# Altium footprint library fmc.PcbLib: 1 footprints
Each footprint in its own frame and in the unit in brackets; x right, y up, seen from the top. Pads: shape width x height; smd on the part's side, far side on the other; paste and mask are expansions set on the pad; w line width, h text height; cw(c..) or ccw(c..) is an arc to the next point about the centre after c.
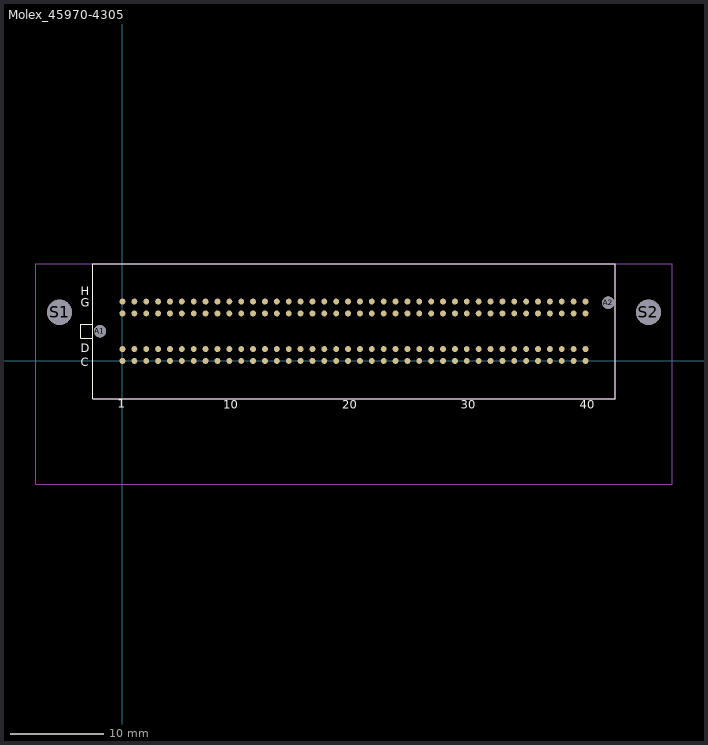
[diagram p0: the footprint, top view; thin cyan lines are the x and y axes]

## Molex_45970-4305 [mm] "1.27mm Pitch, SEARAY* Plug, 400 Circuits, 3.50mm Unmated Height, 10 Rows, with Pegs, Solder Charge™ Lead-Free, with Voids, per VITA-57"
pads (164):
  round 0.63 smd: 1(0,0) C2(1.27,0) C3(2.54,0) C4(3.81,0) C5(5.08,0) C6(6.35,0) C7(7.62,0) C8(8.89,0) C9(10.16,0) C10(11.43,0) C11(12.7,0) C12(13.97,0) C13(15.24,0) C14(16.51,0) C15(17.78,0) C16(19.05,0) C17(20.32,0) C18(21.59,0) C19(22.86,0) C20(24.13,0) C21(25.4,0) C22(26.67,0) C23(27.94,0) C24(29.21,0) C25(30.48,0) C26(31.75,0) C27(33.02,0) C28(34.29,0) C29(35.56,0) C30(36.83,0) C31(38.1,0) C32(39.37,0) C33(40.64,0) C34(41.91,0) C35(43.18,0) C36(44.45,0) C37(45.72,0) C38(46.99,0) C39(48.26,0) C40(49.53,0) D1(0,1.27) D2(1.27,1.27) D3(2.54,1.27) D4(3.81,1.27) D5(5.08,1.27) D6(6.35,1.27) D7(7.62,1.27) D8(8.89,1.27) D9(10.16,1.27) D10(11.43,1.27) D11(12.7,1.27) D12(13.97,1.27) D13(15.24,1.27) D14(16.51,1.27) D15(17.78,1.27) D16(19.05,1.27) D17(20.32,1.27) D18(21.59,1.27) D19(22.86,1.27) D20(24.13,1.27) D21(25.4,1.27) D22(26.67,1.27) D23(27.94,1.27) D24(29.21,1.27) D25(30.48,1.27) D26(31.75,1.27) D27(33.02,1.27) D28(34.29,1.27) D29(35.56,1.27) D30(36.83,1.27) D31(38.1,1.27) D32(39.37,1.27) D33(40.64,1.27) D34(41.91,1.27) D35(43.18,1.27) D36(44.45,1.27) D37(45.72,1.27) D38(46.99,1.27) D39(48.26,1.27) D40(49.53,1.27) G1(0,5.08) G2(1.27,5.08) G3(2.54,5.08) G4(3.81,5.08) G5(5.08,5.08) G6(6.35,5.08) G7(7.62,5.08) G8(8.89,5.08) G9(10.16,5.08) G10(11.43,5.08) G11(12.7,5.08) G12(13.97,5.08) G13(15.24,5.08) G14(16.51,5.08) G15(17.78,5.08) G16(19.05,5.08) G17(20.32,5.08) G18(21.59,5.08) G19(22.86,5.08) G20(24.13,5.08) G21(25.4,5.08) G22(26.67,5.08) G23(27.94,5.08) G24(29.21,5.08) G25(30.48,5.08) G26(31.75,5.08) G27(33.02,5.08) G28(34.29,5.08) G29(35.56,5.08) G30(36.83,5.08) G31(38.1,5.08) G32(39.37,5.08) G33(40.64,5.08) G34(41.91,5.08) G35(43.18,5.08) G36(44.45,5.08) G37(45.72,5.08) G38(46.99,5.08) G39(48.26,5.08) G40(49.53,5.08) H1(0,6.35) H2(1.27,6.35) H3(2.54,6.35) H4(3.81,6.35) H5(5.08,6.35) H6(6.35,6.35) H7(7.62,6.35) H8(8.89,6.35) H9(10.16,6.35) H10(11.43,6.35) H11(12.7,6.35) H12(13.97,6.35) H13(15.24,6.35) H14(16.51,6.35) H15(17.78,6.35) H16(19.05,6.35) H17(20.32,6.35) H18(21.59,6.35) H19(22.86,6.35) H20(24.13,6.35) H21(25.4,6.35) H22(26.67,6.35) H23(27.94,6.35) H24(29.21,6.35) H25(30.48,6.35) H26(31.75,6.35) H27(33.02,6.35) H28(34.29,6.35) H29(35.56,6.35) H30(36.83,6.35) H31(38.1,6.35) H32(39.37,6.35) H33(40.64,6.35) H34(41.91,6.35) H35(43.18,6.35) H36(44.45,6.35) H37(45.72,6.35) H38(46.99,6.35) H39(48.26,6.35) H40(49.53,6.35)
  round 1.321 hole 1.321 unplated: A1(-2.413,3.175) A2(51.956,6.223)
  round 2.692 hole 2.692 unplated: S1(-6.731,5.207) S2(56.261,5.207)
Top Overlay:
  lines w0.127: -3.175,2.413 -3.175,3.937 ; -3.175,2.413 -3.175,-4.064 52.705,-4.064 52.705,10.414 -3.175,10.414 -3.175,3.937 ; -3.175,2.413 -4.445,2.413 -4.445,3.937 -3.175,3.937
  text "C" at -4.445,-0.889 h1.52
  text "D" at -4.445,0.635 h1.52
  text "G" at -4.445,5.461 h1.52
  text "H" at -4.445,6.731 h1.52
  text "1" at -0.508,-5.334 h1.52
  text "10" at 10.795,-5.461 h1.52
  text "20" at 23.495,-5.461 h1.52
  text "30" at 36.195,-5.461 h1.52
  text "40" at 48.895,-5.461 h1.52
Mechanical 3:
  lines w0.1: -9.271,-13.208 -9.271,10.414 58.801,10.414 58.801,-13.208 -9.271,-13.208
Mechanical 15:
  lines w0.1: -3.175,-4.013 -3.124,-4.064 52.68,-4.064 52.705,-4.039 52.705,10.414 -3.175,10.414 -3.175,-4.013
3D body "Molex-45970-4305.step": height 7.11, standoff -1.27, extent -4.724,-4.165 52.654,10.516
